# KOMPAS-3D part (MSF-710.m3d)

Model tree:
1. Ось X
2. Ось Y
3. Ось Z
4. Начало координат  (labels: Операция без истории:1)

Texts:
  Линия-выноска #1
  Линия-выноска #2
  Линия-выноска #3
  Отклонения формы и база
  Марка координационной оси
  Марка/позиционное обозначение с линией-выноской
  Марка/позиционное обозначение на линии
  Марка/позиционное обозначение без линии-выноски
